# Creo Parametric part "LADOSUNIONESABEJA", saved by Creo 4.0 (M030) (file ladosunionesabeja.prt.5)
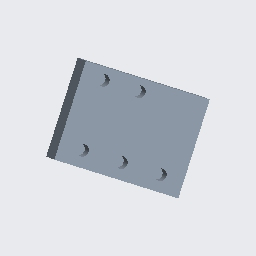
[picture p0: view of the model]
Units: millimeter Newton Second (mmNs); MM, TONNE, SECS

Created from: MMNS_PART_SOLID.PRT

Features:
  1. datum plane "RIGHT"
  2. datum plane "TOP"
  3. datum plane "FRONT"
  4. coordinate system
  5. sketch "Sketch 1"
  6. extrusion "Extrude 1"
  7. pattern "Pattern 1"
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
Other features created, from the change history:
  hole "Hole 1"
  hole "Hole 1 [2]"
  hole "Hole 1 [3]"
  hole "Hole 2"
  pattern "Patrón 2"
  hole "Taladro 2 [2]"
  hole "Hole 3"
  pattern "Pattern 3"
  hole "Hole 3 [2]"

Surfaces: 13 plane, 7 cylinder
